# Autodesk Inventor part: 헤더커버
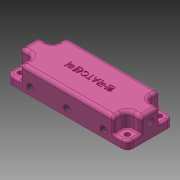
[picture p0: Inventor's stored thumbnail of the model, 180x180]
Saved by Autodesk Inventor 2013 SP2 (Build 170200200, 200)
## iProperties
Created: 2015-11
Part Number: 헤더커버
Material: 알루미늄 6061
Document SubType Name: Modeling
Designer: mduedu
Density: 2.71 g/cm^3
Author: mduedu
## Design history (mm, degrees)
sketch "스케치1"
  geometry: L1 (52.5, 20)-(-52.5, 20); L2 (-52.5, 20)-(-52.5, -20); L3 (-52.5, -20)-(52.5, -20); L4 (52.5, -20)-(52.5, 20); L5 (52.5, 20)-(-52.5, -20); L6 (-52.5, 20)-(52.5, -20); 1 further point
  constraints: 12 end point, 2 midpoint, 2 parallel, 1 horizontal, 1 perpendicular
  dimensions: "d0" = 105 distance of L3.end L2.end; "d1" = 40 distance of L2.end L1.end
extrude "돌출1" new body sketch "스케치1" distance "d2" = 20; taper "d3" = 0 deg
sketch "스케치2"
  geometry: L1 (-52.5, -20)-(-52.5, 20) reference; L2 (-52.5, 20)-(52.5, 20) reference; L3 (52.5, 20)-(52.5, -20) reference; L4 (52.5, -20)-(-52.5, -20) reference; L5 (-52.5, 20)-(-40.5, 20); L6 (-40.5, 20)-(-40.5, 8); L7 (-40.5, 8)-(-52.5, 8); L8 (-52.5, 8)-(-52.5, 20); L9 (52.5, 20)-(40.5, 20); L10 (40.5, 20)-(40.5, 8); L11 (40.5, 8)-(52.5, 8); L12 (52.5, 8)-(52.5, 20); L13 (52.5, -20)-(40.5, -20); L14 (40.5, -20)-(40.5, -8); L15 (40.5, -8)-(52.5, -8); L16 (52.5, -8)-(52.5, -20); L17 (-52.5, -20)-(-40.5, -20); L18 (-40.5, -20)-(-40.5, -8); L19 (-40.5, -8)-(-52.5, -8); L20 (-52.5, -8)-(-52.5, -20); 1 further point
  constraints: 32 end point, 8 parallel, 6 equal length, 4 horizontal, 4 perpendicular
  dimensions: "d4" = 12 distance of L6.end L7.end; "d5" = 12 distance of L5.end L6.end
extrude "돌출2" cut sketch "스케치2" distance "d6" = 13; taper "d7" = 0 deg
fillet "모깎기1" dims "d8" = 5
fillet "모깎기2" dims "d9" = 1
fillet "모깎기3" dims "d10" = 5
fillet "모깎기4" dims "d11" = 2
fillet "모깎기5" dims "d12" = 3
sketch "스케치3"
  geometry: L1 (-46.5, -14)-(46.5, -14); L2 (46.5, -14)-(46.5, 14); L3 (46.5, 14)-(-46.5, 14); L4 (-46.5, 14)-(-46.5, -14); L5 (-46.5, -14)-(46.5, 14); L6 (46.5, -14)-(-46.5, 14); L7 (47.5, 20)-(-47.5, 20) reference; L8 (52.5, -15)-(52.5, 15) reference; 5 further points
  constraints: 12 end point, 4 coincident, 2 midpoint, 2 parallel, 1 horizontal, 1 perpendicular
  dimensions: "d13" = 6 distance between parallel lines of L3 L7; "d14" = 6 distance between parallel lines of L2 L8
hole "구멍1" sketch "스케치3" at (-46.5, 14), (46.5, 14), (46.5, -14), (-46.5, -14) diameter "d15" = 4.5; stored, may be unused: countersink angle "d19" = 90 deg, drill point angle "d21" = 118 deg; dims "d16" = 6, "d17" = 4, "d18" = 2, "d20" = 8
sketch "스케치4"
  geometry: L1 (47.5, -20)-(-47.5, -20) reference; L2 (52.5, 15)-(52.5, -15) reference; L3 (-47.5, 20)-(47.5, 20) reference; L4 (-52.5, -15)-(-52.5, 15) reference; L5 (-52.5, 0)-(52.5, 0); C1 r 12.25 at (0, 0); C2 r 2.25 at (46.5, 14) reference; C3 r 2.25 at (-46.5, -14) reference; C4 r 2.25 at (46.5, -14) reference; C5 r 2.25 at (-46.5, 14) reference; C6 r 12.25 at (-32, 0); C7 r 12.25 at (32, 0); A1 r 5 centre (-47.5, -15) between (-52.5, -15) and (-47.5, -20) reference; A2 r 5 centre (47.5, -15) between (47.5, -20) and (52.5, -15) reference; A3 r 5 centre (47.5, 15) between (52.5, 15) and (47.5, 20) reference; A4 r 5 centre (-47.5, 15) between (-47.5, 20) and (-52.5, 15) reference; 1 further point
  constraints: 3 centre point, 2 end point, 2 midpoint, 2 point on line, 1 coincident
  dimensions: "d22" = 24.5 diameter of C1; "d23" = 24.5 diameter of C7 (= d22); "d24" = 24.5 diameter of C6 (= d22); "d25" = 32 distance of point (0, 0) C6.centre; "d26" = 32 distance of C7.centre point (0, 0) (= d25)
extrude "돌출3" cut sketch "스케치4" distance "d27" = 9; taper "d28" = 0 deg
fillet "모깎기6" dims "d29" = 5
sketch "스케치5"
  geometry: L1 (-52.5, 12)-(-47.119, 12); L2 (-40.191, 8)-(-37.635, 3.574); L3 (-52.5, 17)-(-52.5, 8) reference; L4 (-47.5, 0)-(-52.5, 0) reference; L5 (37.5, 20)-(-37.5, 20) reference; L6 (0, 0)-(0, 20); L7 (52.5, 12)-(47.119, 12); L8 (40.191, 8)-(37.635, 3.574); A1 r 8 centre (-47.119, 4) between (-40.191, 8) and (-47.119, 12); A2 r 8 centre (47.119, 4) between (47.119, 12) and (40.191, 8); 1 further point
  constraints: 10 end point, 5 symmetric about line, 4 point on circle, 3 point on line, 2 centre point, 2 tangent, 1 horizontal, 1 midpoint, 1 other
  dimensions: "d30" = 10 distance of L1.start point (-42.5, 12); "d32" = 120 deg angle of L2 L1; "d34" = 12 distance between parallel lines of L1 L4; "d35" = 8 radius of A1
sketch "스케치6"
  geometry: L1 (20, -5)-(20, 5) reference; L2 (8, -20)-(17, -20) reference; L3 (12, -20)-(12, -14.619); L4 (8, -7.691)-(3.81, -5.272); L5 (0, -20)-(0, -15) reference; A1 r 8 centre (4, -14.619) between (12, -14.619) and (8, -7.691); 2 further points
  constraints: 4 end point, 3 point on line, 2 point on circle, 2 tangent, 1 centre point, 1 perpendicular
  dimensions: "d36" = 10 distance of L3.start point (12, -10); "d38" = 12 distance between parallel lines of L3 L5; "d39" = 120 deg angle of L3 L4; "d40" = 8 radius of A1
node "작업점1"
node "작업점2"
node "작업점3"
hole "구멍2" diameter "d43" = 5.944; stored, may be unused: countersink angle "d49" = 90 deg, drill point angle "d51" = 0 deg; dims "d41" = 10, "d42" = 10, "d44" = 6.886, "d45" = 0.62479, "d46" = 5.959, "d47" = 4, "d48" = 2, "d50" = 6.9
hole "구멍3" diameter "d54" = 5.944; stored, may be unused: countersink angle "d60" = 90 deg, drill point angle "d62" = 0 deg; dims "d52" = 10, "d53" = 10, "d55" = 6.886, "d56" = 0.62479, "d57" = 5.959, "d58" = 4, "d59" = 2, "d61" = 6.9
hole "구멍4" diameter "d65" = 5.944; stored, may be unused: countersink angle "d71" = 90 deg, drill point angle "d73" = 0 deg; dims "d63" = 10, "d64" = 10, "d66" = 6.886, "d67" = 0.62479, "d68" = 5.959, "d69" = 4, "d70" = 2, "d72" = 6.9
sketch "스케치7"
  geometry: C1 r 2.972 at (15, 12) reference; 1 further point
sketch "스케치8"
  geometry: C1 r 2.972 at (15, 12) reference; 1 further point
sketch "스케치9"
  geometry: C1 r 2.972 at (47.5, 12) reference; 1 further point
feature "스윕1" dims "d74" = 0
feature "스윕2" dims "d75" = 0
feature "스윕3" dims "d76" = 0
sketch "스케치10"
  geometry: L1 (0, 0)-(95, 0) reference; L2 (54.75, 9)-(40.25, 9) reference; L3 (15.723, 9)-(15.723, 0); L4 (47.5, 9)-(47.5, 0); L5 (79.277, 9)-(79.277, 0); 9 further points; 2 other entities
  constraints: 6 end point, 5 point on line, 2 horizontal alignment, 2 perpendicular, 1 midpoint, 1 parallel, 4 other
  dimensions: "d77" = 6 distance from line of point (15.723, 6) L1
hole "구멍5" sketch "스케치10" at (15.723, 6), (47.5, 6), (79.277, 6) diameter "d78" = 5.944; stored, may be unused: countersink angle "d84" = 90 deg, drill point angle "d86" = 0 deg; dims "d79" = 6.886, "d80" = 0.62479, "d81" = 5.959, "d82" = 4, "d83" = 2, "d85" = 6.9
sketch "스케치11"
  geometry: C1 r 2.972 at (0, 0) reference; C2 r 2.972 at (31.777, 0) reference; C3 r 2.972 at (63.554, 0) reference; 1 further point
extrude "돌출4" cut sketch "스케치11" distance "d87" = 8; taper "d88" = 0 deg
sketch "스케치12"
  geometry: 2 further points
  constraints: 1 coincident, 1 other
feature "엠보싱1" sketch "스케치12" dims "d0" = 105, "d1" = 40, "d4" = 12, "d5" = 12, "d89" = 0.5, "d90" = 0
node "솔리드1"
node "투영된 루프1"
node "절단 모서리 투영1"
